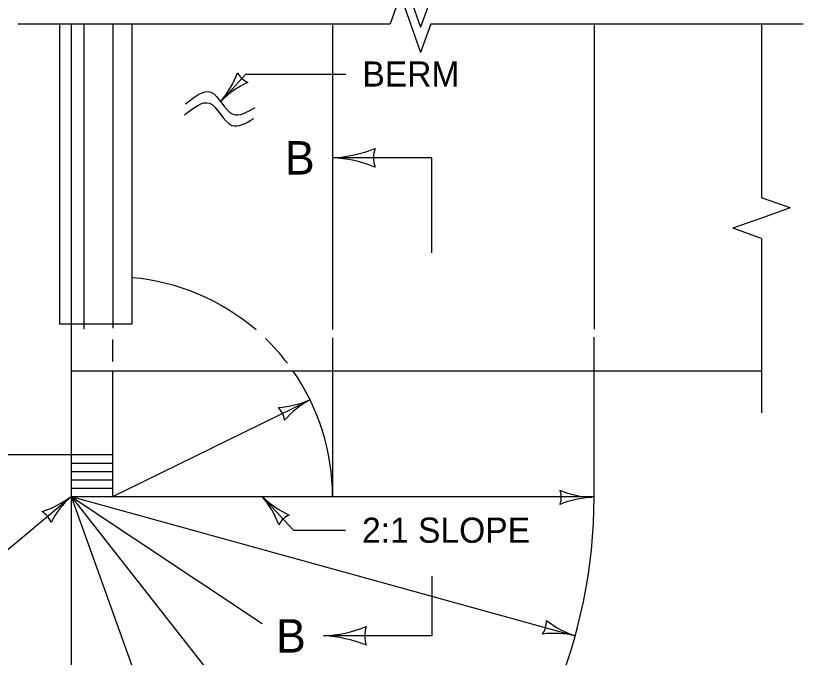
# Model space of a CAD drawing. Extents: x 49991.4 to 50021, y 49987.6 to 50011.4.
# Drawn here: x 50001.915 to 50003.797, y 50003.923 to 50005.456 of the extents above; entities that cross this region are included whole.
import ezdxf

# ---------------------------------------------------------------- set-up
doc = ezdxf.new("R2010")
doc.units = 0
for name, color, linetype in [('Level 1', 7, 'Continuous'), ('Level 2', 7, 'Continuous'), ('Level 3', 7, 'Continuous'), ('Level 4', 7, 'Continuous'), ('Level 6', 7, 'Continuous')]:
    doc.layers.add(name, color=color, linetype=linetype)

msp = doc.modelspace()

# ---------------------------------------------------------------- linework, layer by layer
at = {"layer": 'Level 1'}
for p, q in [((50002.0471, 50005.437), (50002.0471, 50004.307)), ((50002.0786, 50004.707), (50002.0786, 50005.437)), ((50003.6971, 50004.607), (50002.0471, 50004.607)), ((50002.1471, 50004.307), (50002.1471, 50004.607)), ((50002.6721, 50004.607), (50002.6721, 50004.307)), ((50003.2971, 50004.307), (50003.2971, 50004.607)), ((50002.1471, 50004.407), (50001.0722, 50004.407)), ((50002.0471, 50004.387), (50002.1471, 50004.387)), ((50002.0471, 50004.367), (50002.1471, 50004.367)), ((50002.0471, 50004.347), (50002.1471, 50004.347)), ((50002.0471, 50004.327), (50002.1471, 50004.327)), ((50002.0471, 50004.307), (50002.1471, 50004.307))]:
    msp.add_line(p, q, dxfattribs=at)
for centre, radius, start, end in [((50002.1471, 50004.307), 0.525, 0, 34.8499), ((50002.0471, 50004.307), 1.25, 270, 0)]:
    msp.add_arc(centre, radius, start, end, dxfattribs=at)
at = {"layer": 'Level 3'}
for p, q in [((50002.4057, 50005.2521), (50002.4652, 50005.3168)), ((50002.4652, 50005.3168), (50002.7035, 50005.3168)), ((50002.1471, 50004.307), (50002.6184, 50004.5384)), ((50001.7521, 50004.06), (50002.0471, 50004.307)), ((50002.0471, 50004.307), (50003.252, 50003.9744)), ((50002.0471, 50004.307), (50002.8198, 50003.3245)), ((50002.0471, 50004.307), (50002.4704, 50003.1309)), ((50002.0471, 50004.307), (50002.5037, 50004.0034)), ((50002.0471, 50004.307), (50002.0471, 50003.057)), ((50002.1471, 50004.307), (50003.2971, 50004.307)), ((50002.504, 50004.307), (50002.5789, 50004.2266)), ((50002.5789, 50004.2266), (50002.7027, 50004.2266))]:
    msp.add_line(p, q, dxfattribs=at)
for centre, radius, start, end in [((50002.2266, 50005.4012), 0.233, 320.2248, 339.4746), ((50002.4925, 50005.3465), 0.0548, 209.5363, 245.2586), ((50002.563, 50005.095), 0.2223, 114.8535, 135.037), ((50002.6568, 50005.4268), 0.3107, 272.8273, 292.0772), ((50002.8431, 50005.1165), 0.073, 162.1388, 197.8612), ((50002.6599, 50004.8203), 0.2964, 67.456, 87.6395), ((50002.5287, 50004.7417), 0.2222, 273.6062, 293.7897), ((50002.7312, 50004.3347), 0.2329, 118.9775, 138.2274), ((50002.5033, 50004.4819), 0.0547, 8.289, 44.0114), ((50003.3013, 50004.5272), 0.2223, 247.456, 267.6395), ((50003.164, 50004.3051), 0.0548, 342.1388, 17.8612), ((50001.9065, 50004.4928), 0.233, 287.8656, 307.1155), ((50002.1967, 50004.1426), 0.2223, 132.3033, 152.4868), ((50002.3348, 50004.162), 0.2229, 20.4277, 40.6112), ((50002.6668, 50004.4745), 0.2336, 225.799, 245.0489), ((50003.3037, 50004.0724), 0.233, 92.8273, 112.0772), ((50001.9488, 50004.2247), 0.0548, 22.0816, 57.804), ((50002.5916, 50004.213), 0.0549, 115.1105, 150.8329), ((50003.1284, 50004.0085), 0.0548, 326.7072, 2.4296), ((50003.32, 50004.1861), 0.2223, 232.0244, 252.2079), ((50002.6356, 50004.2842), 0.3107, 272.8273, 292.0772), ((50002.8219, 50003.9739), 0.073, 162.1388, 197.8612), ((50002.6387, 50003.6778), 0.2964, 67.456, 87.6395), ((50003.2012, 50003.747), 0.233, 77.3957, 96.6456)]:
    msp.add_arc(centre, radius, start, end, dxfattribs=at)
at = {"layer": 'Level 4'}
for p, q in [((50002.0198, 50005.437), (50002.0198, 50004.7194)), ((50002.1471, 50005.437), (50002.1471, 50004.7091)), ((50002.1933, 50004.7194), (50002.1933, 50005.437)), ((50002.6721, 50005.4367), (50002.6721, 50004.7064)), ((50003.2971, 50005.437), (50003.2971, 50004.7067)), ((50002.0198, 50004.7194), (50002.1933, 50004.7194)), ((50003.2971, 50004.607), (50003.2971, 50004.6879)), ((50002.1471, 50004.6298), (50002.1471, 50004.6826)), ((50002.6721, 50004.6862), (50002.6721, 50004.607))]:
    msp.add_line(p, q, dxfattribs=at)
for start, end in [(49.3262, 84.9524), (37.3452, 45.9651)]:
    msp.add_arc((50002.1471, 50004.307), 0.525, start, end, dxfattribs=at)
at = {"layer": 'Level 6'}
for p, q in [((50002.8341, 50005.5055), (50002.8098, 50005.437)), ((50002.8341, 50005.5055), (50002.8584, 50005.437)), ((50002.8584, 50005.497), (50002.8827, 50005.4285)), ((50002.907, 50005.497), (50002.8827, 50005.4285)), ((50001.9198, 50005.437), (50002.8098, 50005.437)), ((50002.8584, 50005.437), (50002.8827, 50005.3685)), ((50002.907, 50005.437), (50002.8827, 50005.3685)), ((50002.907, 50005.437), (50003.7971, 50005.437)), ((50003.6971, 50005.437), (50003.6971, 50005.0209)), ((50002.9098, 50005.1165), (50002.6721, 50005.1165)), ((50002.9098, 50004.8892), (50002.9098, 50005.1165)), ((50003.7656, 50004.9966), (50003.6971, 50005.0209)), ((50003.7656, 50004.9966), (50003.6971, 50004.9723)), ((50003.6971, 50004.9723), (50003.6286, 50004.948)), ((50003.6971, 50004.9237), (50003.6286, 50004.948)), ((50003.6971, 50004.9237), (50003.6971, 50004.507)), ((50002.9098, 50004.117), (50002.9098, 50003.9739)), ((50002.9098, 50003.9739), (50002.6509, 50003.9739))]:
    msp.add_line(p, q, dxfattribs=at)
for points in [[(50002.321, 50005.2454), (50002.3812, 50005.2733), (50002.4342, 50005.2205), (50002.4871, 50005.2366)], [(50002.3181, 50005.219), (50002.3783, 50005.2469), (50002.4313, 50005.1941), (50002.4842, 50005.2102)]]:
    msp.add_spline(points, degree=3, dxfattribs=at)

# ---------------------------------------------------------------- texts
at = {"layer": 'Level 2'}
for s, height, p in [('BERM', 0.06, (50002.7435, 50005.2868)), ('B', 0.0799, (50002.5582, 50005.0765)), ('2:1 SLOPE', 0.06, (50002.7427, 50004.1966)), ('B', 0.0799, (50002.537, 50003.934))]:
    msp.add_text(s, height=height, dxfattribs=at).set_placement(p)

doc.saveas('drawing.dxf')
